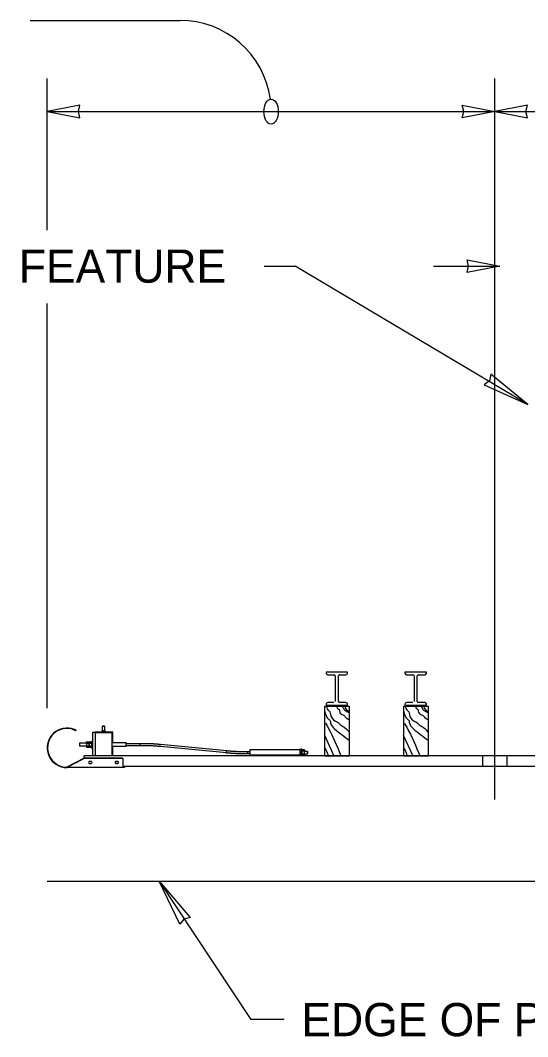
# Model space of a CAD drawing. Extents: x 99862 to 103680, y 99470 to 102076.
# Drawn here: x 100704.8 to 100949.2, y 100910.7 to 101400.9 of the extents above; entities that cross this region are included whole.
import ezdxf

# ---------------------------------------------------------------- set-up
doc = ezdxf.new("R2010")
doc.units = 0
for name, color, linetype in [('Level 10', 7, 'Continuous'), ('Level 11', 7, 'Continuous'), ('Level 13', 7, 'Continuous'), ('Level 15', 7, 'Continuous'), ('Level 2', 7, 'Continuous'), ('Level 20', 7, 'Continuous'), ('Level 21', 7, 'Continuous'), ('Level 3', 7, 'Continuous'), ('Level 4', 7, 'Continuous'), ('Level 5', 7, 'Continuous'), ('Level 6', 7, 'Continuous'), ('Level 7', 7, 'Continuous'), ('Level 9', 7, 'Continuous')]:
    doc.layers.add(name, color=color, linetype=linetype)

msp = doc.modelspace()

# ---------------------------------------------------------------- linework, layer by layer
at = {"layer": 'Level 10'}
for p, q in [((100851.41, 101070.07), (100863.41, 101070.07)), ((100851.41, 101070.07), (100851.41, 101046.07)), ((100863.41, 101046.07), (100863.41, 101070.07)), ((100889.41, 101070.07), (100901.41, 101070.07)), ((100889.41, 101070.07), (100889.41, 101046.07)), ((100901.41, 101046.07), (100901.41, 101070.07)), ((100851.41, 101046.07), (100863.41, 101046.07)), ((100856.47, 101045.99), (100856.47, 101046.07)), ((100856.47, 101045.99), (100856.47, 101046.07)), ((100858.34, 101046.07), (100858.34, 101045.99)), ((100858.34, 101046.07), (100858.34, 101045.99)), ((100889.41, 101046.07), (100901.41, 101046.07)), ((100894.47, 101045.99), (100894.47, 101046.07)), ((100894.47, 101045.99), (100894.47, 101046.07)), ((100896.34, 101046.07), (100896.34, 101045.99)), ((100896.34, 101046.07), (100896.34, 101045.99))]:
    msp.add_line(p, q, dxfattribs=at)
at = {"layer": 'Level 11'}
for p, q in [((100927.46, 101046.07), (100927.46, 101040.99)), ((100939.23, 101046.07), (100939.23, 101040.99))]:
    msp.add_line(p, q, dxfattribs=at)
at = {"layer": 'Level 13'}
for p, q in [((100851.28, 101056.16), (100855.88, 101046.15)), ((100889.28, 101056.16), (100893.88, 101046.15))]:
    msp.add_line(p, q, dxfattribs=at)
for points in [[(100852.16, 101070.06), (100853.44, 101067.79), (100853.89, 101067.38), (100854.24, 101065.99), (100856.37, 101062.97), (100858.28, 101061.88), (100858.69, 101061.34), (100860.82, 101059.88), (100861, 101059.75), (100863.42, 101057.46)], [(100857.13, 101070.06), (100857.95, 101068.71), (100858.35, 101068.54), (100858.52, 101067.83), (100859.76, 101066.06), (100861, 101065.4), (100861.32, 101064.97), (100863.38, 101063.56)], [(100859.83, 101070.08), (100860.24, 101069.39), (100861.15, 101068.1), (100862.14, 101067.51), (100863.31, 101066.77)], [(100861.24, 101070.05), (100861.6, 101068.73), (100863.31, 101067.6)], [(100890.16, 101070.06), (100891.44, 101067.79), (100891.89, 101067.38), (100892.24, 101065.99), (100894.37, 101062.97), (100896.28, 101061.88), (100896.69, 101061.34), (100898.82, 101059.88), (100899, 101059.75), (100901.42, 101057.46)], [(100895.13, 101070.06), (100895.95, 101068.71), (100896.35, 101068.54), (100896.52, 101067.83), (100897.76, 101066.06), (100899, 101065.4), (100899.32, 101064.97), (100901.38, 101063.56)], [(100897.83, 101070.08), (100898.24, 101069.39), (100899.15, 101068.1), (100900.14, 101067.51), (100901.31, 101066.77)], [(100899.24, 101070.05), (100899.6, 101068.73), (100901.31, 101067.6)], [(100851.35, 101067.81), (100853.45, 101063.66), (100853.9, 101063.26), (100854.25, 101061.87), (100856.2, 101059.15), (100863.41, 101053.56)], [(100889.35, 101067.81), (100891.45, 101063.66), (100891.9, 101063.26), (100892.25, 101061.87), (100894.2, 101059.15), (100901.41, 101053.56)], [(100851.81, 101061.95), (100852.96, 101059.94), (100859.37, 101046.01)], [(100889.81, 101061.95), (100890.96, 101059.94), (100897.37, 101046.01)], [(100851.39, 101050.24), (100851.54, 101049.98), (100851.68, 101049.71), (100851.96, 101049.17), (100852.44, 101048.06), (100852.9, 101046.93), (100853.13, 101046.37), (100853.37, 101045.81)], [(100889.39, 101050.24), (100889.54, 101049.98), (100889.68, 101049.71), (100889.96, 101049.17), (100890.44, 101048.06), (100890.9, 101046.93), (100891.13, 101046.37), (100891.37, 101045.81)]]:
    msp.add_spline(points, degree=3, dxfattribs=at)
at = {"layer": 'Level 15'}
for p, q in [((100933.41, 101025.04), (100933.41, 101372.87)), ((100822.19, 101282.31), (100837.28, 101282.31)), ((100949.27, 101215.58), (100837.28, 101282.31)), ((100771.65, 100985.62), (100815.84, 100918.9)), ((100831.84, 100918.9), (100815.84, 100918.9))]:
    msp.add_line(p, q, dxfattribs=at)
for points in [[(100949.27, 101215.58), (100931.42, 101230.12), (100930.75, 101227.03), (100928.28, 101225.04)], [(100771.65, 100985.62), (100786.67, 100968.17), (100783.6, 100967.42), (100781.68, 100964.9)]]:
    msp.add_lwpolyline(points, close=True, dxfattribs=at)
msp.add_ellipse((100825.59, 101356.85), major_axis=(0, -6), ratio=0.57735, dxfattribs=at)
at = {"layer": 'Level 2'}
for p, q in [((100735.54, 101046.04), (100735.54, 101046.07)), ((100965.53, 101046.07), (100735.54, 101046.07)), ((100735.54, 101044.99), (100735.54, 101046.04)), ((100960.44, 101040.98), (100754.27, 101040.98))]:
    msp.add_line(p, q, dxfattribs=at)
at = {"layer": 'Level 20'}
for p, q in [((100709.47, 101400.85), (100781.68, 101400.85)), ((100717.77, 101299.67), (100717.77, 101372.87)), ((100717.77, 101356.85), (100933.41, 101356.85)), ((100933.41, 101356.85), (101283.16, 101356.85)), ((100903.77, 101282.31), (100935.77, 101282.31)), ((100717.77, 101069.13), (100717.77, 101264.31))]:
    msp.add_line(p, q, dxfattribs=at)
for points in [[(100717.77, 101356.85), (100733.5, 101353.77), (100732.77, 101356.85), (100733.5, 101359.94)], [(100933.41, 101356.85), (100917.68, 101353.77), (100918.41, 101356.85), (100917.68, 101359.94)], [(100933.41, 101356.85), (100949.13, 101353.77), (100948.4, 101356.85), (100949.13, 101359.94)], [(100935.77, 101282.31), (100920.05, 101279.23), (100920.77, 101282.31), (100920.05, 101285.39)]]:
    msp.add_lwpolyline(points, close=True, dxfattribs=at)
msp.add_arc((100781.68, 101356.85), 44, 7.8051, 90, dxfattribs=at)
at = {"layer": 'Level 21'}
msp.add_line((101213.04, 100985.46), (100717.77, 100985.46), dxfattribs=at)
at = {"layer": 'Level 3'}
for p, q in [((100744.44, 101060.44), (100744.57, 101060.57)), ((100744.44, 101060.44), (100745.38, 101060.44)), ((100744.44, 101058.26), (100744.44, 101060.44)), ((100744.57, 101060.57), (100745.25, 101060.57)), ((100745.25, 101060.57), (100745.38, 101060.44)), ((100745.38, 101060.44), (100745.38, 101058.26)), ((100729.52, 101059.29), (100729.48, 101059.1)), ((100731.68, 101058.47), (100731.6, 101058.31)), ((100735.52, 101044.99), (100727.27, 101040.62)), ((100753.89, 101044.99), (100735.52, 101044.99)), ((100753.89, 101044.88), (100735.57, 101044.88)), ((100738.68, 101043.47), (100738.35, 101043.47)), ((100738.68, 101042.37), (100738.35, 101042.37)), ((100751.43, 101043.47), (100751.1, 101043.47)), ((100751.43, 101042.37), (100751.1, 101042.37)), ((100754.27, 101044.58), (100754.27, 101044.69)), ((100754.27, 101041.15), (100754.27, 101044.58)), ((100754.27, 101041.15), (100754.27, 101040.43)), ((100754.27, 101040.43), (100735.52, 101040.43))]:
    msp.add_line(p, q, dxfattribs=at)
for radius, end in [(9.56, 270.2805), (9.37, 270)]:
    msp.add_arc((100727.27, 101049.99), radius, 76.3846, end, dxfattribs=at)
for centre, major_axis, start_param, end_param in [((100738.35, 101042.92), (0.68, 0), 1.570796, 4.712389), ((100738.68, 101042.92), (0.68, 0), 4.712389, 7.853982), ((100751.1, 101042.92), (0.68, 0), 1.570796, 4.712389), ((100751.43, 101042.92), (0.68, 0), 4.712389, 7.853982), ((100753.89, 101044.69), (-0.375, 0), 3.141593, 4.712389), ((100753.89, 101044.58), (-0.375, 0), 3.141593, 4.712389)]:
    msp.add_ellipse(centre, major_axis=major_axis, ratio=0.807578, start_param=start_param, end_param=end_param, dxfattribs=at)
for points, degree in [([(100729.48, 101059.1), (100729.56, 101059.08), (100729.73, 101059.04), (100729.97, 101058.97), (100730.2, 101058.9), (100730.42, 101058.82), (100730.63, 101058.75), (100730.82, 101058.67), (100731.08, 101058.56), (100731.35, 101058.43), (100731.56, 101058.33), (100731.59, 101058.31), (100731.6, 101058.31)], 3), ([(100729.52, 101059.29), (100730.75, 101058.99), (100731.68, 101058.47), (100731.68, 101058.47)], 2), ([(100735.57, 101044.88), (100732.84, 101043.39), (100730.1, 101041.91), (100727.36, 101040.45), (100727.34, 101040.45), (100727.33, 101040.44), (100727.32, 101040.43)], 3), ([(100754.64, 101040.72), (100754.61, 101040.7), (100754.55, 101040.67), (100754.47, 101040.64), (100754.37, 101040.62), (100754.31, 101040.62), (100754.27, 101040.62)], 3), ([(100755.09, 101040.98), (100754.8, 101040.81), (100754.64, 101040.72)], 2), ([(100755.46, 101040.98), (100755.32, 101040.89), (100755.19, 101040.82), (100754.9, 101040.65), (100754.74, 101040.56)], 3), ([(100735.52, 101040.43), (100732.77, 101040.43), (100730.02, 101040.43), (100727.27, 101040.43)], 2), ([(100727.32, 101040.43), (100727.32, 101040.43), (100727.32, 101040.43), (100727.32, 101040.43)], 2), ([(100754.74, 101040.56), (100754.59, 101040.47), (100754.46, 101040.43), (100754.27, 101040.43)], 2), ([(100754.27, 101040.43), (100754.27, 101040.43), (100754.27, 101040.43), (100754.27, 101040.43)], 2)]:
    msp.add_open_spline(points, degree=degree, dxfattribs=at)
at = {"layer": 'Level 4'}
for p, q in [((100744.1, 101057.57), (100740.79, 101057.57)), ((100742.66, 101057.29), (100740.79, 101057.29)), ((100749.04, 101057.19), (100740.79, 101057.19)), ((100740.79, 101057.19), (100740.79, 101046.07)), ((100749.41, 101057.57), (100745.72, 101057.57)), ((100749.13, 101057.29), (100747.16, 101057.29)), ((100749.04, 101046.07), (100749.04, 101057.19)), ((100749.13, 101052.51), (100749.13, 101057.29)), ((100749.41, 101052.51), (100749.41, 101057.57)), ((100749.13, 101046.07), (100749.13, 101050.63)), ((100749.41, 101046.07), (100749.41, 101050.63))]:
    msp.add_line(p, q, dxfattribs=at)
at = {"layer": 'Level 5'}
for p, q in [((100747.16, 101057.44), (100742.66, 101057.44)), ((100742.66, 101057.44), (100742.66, 101057.19)), ((100747.16, 101057.44), (100747.16, 101057.19))]:
    msp.add_line(p, q, dxfattribs=at)
at = {"layer": 'Level 6'}
for p, q in [((100733.41, 101052.19), (100733.54, 101052.32)), ((100733.41, 101050.95), (100733.41, 101052.19)), ((100733.41, 101052.19), (100733.41, 101052.19)), ((100733.54, 101050.82), (100733.41, 101050.95)), ((100733.54, 101050.82), (100733.54, 101052.32)), ((100733.54, 101052.32), (100736.69, 101052.32)), ((100736.69, 101050.82), (100733.54, 101050.82)), ((100749.04, 101052.51), (100755.82, 101052.51)), ((100755.82, 101050.63), (100749.04, 101050.63)), ((100755.82, 101050.63), (100755.82, 101052.51)), ((100755.82, 101052.51), (100755.82, 101052.51)), ((100755.82, 101052.13), (100762.37, 101052.13)), ((100762.37, 101051.01), (100755.82, 101051.01)), ((100762.37, 101052.13), (100762.37, 101051.01)), ((100804.16, 101047.52), (100772.3, 101050.58)), ((100772.4, 101051.7), (100804.27, 101048.64)), ((100814.2, 101048.21), (100814.2, 101047.09)), ((100814.2, 101048.21), (100815.41, 101048.21)), ((100815.41, 101047.09), (100814.2, 101047.09)), ((100815.41, 101049.19), (100839.41, 101049.19)), ((100815.41, 101049.19), (100815.41, 101046.56)), ((100815.41, 101046.56), (100839.41, 101046.56)), ((100815.41, 101046.56), (100815.41, 101046.07)), ((100839.41, 101049.34), (100840.16, 101049.34)), ((100839.41, 101049.34), (100839.41, 101046.07)), ((100840.16, 101049.34), (100840.16, 101046.07)), ((100841.72, 101048.4), (100843.02, 101048.4)), ((100843.02, 101046.9), (100841.72, 101046.9)), ((100843.02, 101048.4), (100843.02, 101046.9)), ((100843.02, 101048.4), (100843.16, 101048.27)), ((100843.16, 101047.03), (100843.02, 101046.9)), ((100843.16, 101048.27), (100843.16, 101047.03)), ((100843.16, 101047.03), (100843.16, 101047.03))]:
    msp.add_line(p, q, dxfattribs=at)
for centre, start_param in [((100772.35, 101051.14), 3.141597), ((100804.22, 101048.08), 3.141588)]:
    msp.add_ellipse(centre, major_axis=(-0.054, -0.56), ratio=0.548823, start_param=start_param, end_param=6.283185, dxfattribs=at)
for points in [[(100762.37, 101052.13), (100765.91, 101052.13), (100769.45, 101051.98), (100772.4, 101051.7)], [(100772.3, 101050.58), (100769.38, 101050.86), (100765.88, 101051.01), (100762.37, 101051.01)], [(100814.2, 101047.09), (100810.66, 101047.09), (100807.12, 101047.24), (100804.16, 101047.52)], [(100804.27, 101048.64), (100807.19, 101048.36), (100810.69, 101048.21), (100814.2, 101048.21)]]:
    msp.add_open_spline(points, degree=2, dxfattribs=at)
at = {"layer": 'Level 7'}
for p, q in [((100739.57, 101057.57), (100739.57, 101046.07)), ((100739.57, 101057.57), (100740.79, 101057.57)), ((100740.79, 101057.57), (100740.79, 101057.19))]:
    msp.add_line(p, q, dxfattribs=at)
at = {"layer": 'Level 9'}
for p, q in [((100856.51, 101084.64), (100856.5, 101078.5)), ((100858.04, 101078.5), (100858.05, 101084.64)), ((100894.51, 101084.64), (100894.5, 101078.5)), ((100896.04, 101078.5), (100896.05, 101084.64)), ((100856.5, 101078.5), (100856.49, 101072.37)), ((100858.04, 101072.37), (100858.04, 101078.5)), ((100894.5, 101078.5), (100894.49, 101072.37)), ((100896.04, 101072.37), (100896.04, 101078.5)), ((100744.1, 101058.2), (100744.21, 101058.26)), ((100744.1, 101058.2), (100744.1, 101057.44)), ((100744.91, 101058.26), (100744.21, 101058.26)), ((100744.51, 101058.2), (100744.51, 101057.44)), ((100745.51, 101058.26), (100744.91, 101058.26)), ((100745.32, 101058.2), (100745.32, 101057.44)), ((100745.38, 101058.78), (100745.38, 101058.78)), ((100745.38, 101058.78), (100745.38, 101058.78)), ((100745.51, 101058.26), (100745.53, 101058.26)), ((100745.61, 101058.26), (100745.53, 101058.26)), ((100745.61, 101058.26), (100745.72, 101058.2)), ((100745.72, 101058.2), (100745.72, 101057.44)), ((100749.04, 101056.54), (100749.13, 101056.54)), ((100749.13, 101055.6), (100749.04, 101055.6)), ((100736.69, 101052.7), (100736.79, 101052.87)), ((100736.69, 101052.7), (100736.69, 101052.56)), ((100736.69, 101052.53), (100736.69, 101052.56)), ((100736.69, 101052.53), (100736.69, 101051.57)), ((100736.69, 101051.57), (100736.69, 101050.45)), ((100736.79, 101050.27), (100736.69, 101050.45)), ((100736.79, 101052.87), (100738, 101052.87)), ((100736.79, 101052.22), (100738, 101052.22)), ((100736.79, 101050.92), (100738, 101050.92)), ((100738, 101052.7), (100738.11, 101052.87)), ((100738, 101052.22), (100738, 101052.87)), ((100738, 101052.53), (100738, 101052.56)), ((100738, 101050.92), (100738, 101052.22)), ((100738, 101051.57), (100738, 101051.57)), ((100738, 101051.57), (100738, 101051.57)), ((100738, 101050.27), (100738, 101050.92)), ((100738.11, 101050.27), (100738, 101050.45)), ((100738.11, 101052.87), (100739.32, 101052.87)), ((100738.11, 101052.22), (100739.32, 101052.22)), ((100738.11, 101050.92), (100739.32, 101050.92)), ((100739.32, 101053.24), (100739.57, 101053.24)), ((100739.32, 101049.9), (100739.32, 101053.24)), ((100739.32, 101052.87), (100739.32, 101053.24)), ((100739.32, 101052.22), (100739.32, 101052.87)), ((100739.32, 101050.92), (100739.32, 101052.22)), ((100739.32, 101050.27), (100739.32, 101050.92)), ((100736.79, 101050.27), (100738, 101050.27)), ((100738.11, 101050.27), (100739.32, 101050.27)), ((100739.32, 101049.9), (100739.57, 101049.9)), ((100840.41, 101049.31), (100840.16, 101049.31)), ((100840.41, 101049.31), (100840.41, 101046.07)), ((100841.62, 101048.95), (100840.41, 101048.95)), ((100840.41, 101048.95), (100840.41, 101048.3)), ((100841.62, 101048.3), (100840.41, 101048.3)), ((100840.41, 101048.3), (100840.41, 101047)), ((100840.41, 101047), (100840.41, 101046.35)), ((100841.62, 101047), (100840.41, 101047)), ((100840.41, 101046.35), (100840.41, 101046.07)), ((100841.62, 101046.35), (100840.41, 101046.35)), ((100841.62, 101048.95), (100841.72, 101048.77)), ((100841.72, 101046.52), (100841.62, 101046.35)), ((100841.72, 101047.65), (100841.72, 101048.77)), ((100841.72, 101046.69), (100841.72, 101047.65)), ((100841.72, 101046.69), (100841.72, 101046.66)), ((100841.72, 101046.52), (100841.72, 101046.66))]:
    msp.add_line(p, q, dxfattribs=at)
for points in [[(100857.28, 101086.5), (100852.11, 101086.51), (100852.11, 101086.03)], [(100852.9, 101085.24), (100855.92, 101085.23)], [(100862.45, 101086.01), (100862.45, 101086.5), (100857.28, 101086.5)], [(100858.64, 101085.23), (100861.66, 101085.23)], [(100895.28, 101086.5), (100890.11, 101086.51), (100890.11, 101086.03)], [(100890.9, 101085.24), (100893.92, 101085.23)], [(100900.45, 101086.01), (100900.45, 101086.5), (100895.28, 101086.5)], [(100896.64, 101085.23), (100899.66, 101085.23)], [(100852.09, 101070.99), (100852.09, 101070.51), (100857.26, 101070.5)], [(100855.9, 101071.78), (100852.88, 101071.78)], [(100857.26, 101070.5), (100862.43, 101070.5), (100862.43, 101070.98)], [(100861.64, 101071.77), (100858.63, 101071.77)], [(100890.09, 101070.99), (100890.09, 101070.51), (100895.26, 101070.5)], [(100893.9, 101071.78), (100890.88, 101071.78)], [(100895.26, 101070.5), (100900.43, 101070.5), (100900.43, 101070.98)], [(100899.64, 101071.77), (100896.63, 101071.77)]]:
    msp.add_lwpolyline(points, dxfattribs=at)
for centre, radius, start, end in [((100852.9, 101086.03), 0.788, 179.9273, 269.9273), ((100855.92, 101084.64), 0.591, 359.9273, 89.9273), ((100858.64, 101084.64), 0.591, 89.9273, 179.9273), ((100861.66, 101086.01), 0.788, 269.9273, 359.9273), ((100890.9, 101086.03), 0.788, 179.9273, 269.9273), ((100893.92, 101084.64), 0.591, 359.9273, 89.9273), ((100896.64, 101084.64), 0.591, 89.9273, 179.9273), ((100899.66, 101086.01), 0.788, 269.9273, 359.9273), ((100852.88, 101070.99), 0.788, 89.9273, 179.9478), ((100858.63, 101072.36), 0.591, 179.9273, 269.9273), ((100861.64, 101070.98), 0.788, 359.9478, 89.9273), ((100890.88, 101070.99), 0.788, 89.9273, 179.9478), ((100896.63, 101072.36), 0.591, 179.9273, 269.9273), ((100899.64, 101070.98), 0.788, 359.9478, 89.9273)]:
    msp.add_arc(centre, radius, start, end, dxfattribs=at)
for points, degree in [([(100744.1, 101058.2), (100744.17, 101058.24), (100744.23, 101058.26), (100744.37, 101058.26), (100744.44, 101058.24), (100744.51, 101058.2)], 3), ([(100744.1, 101058.2), (100744.1, 101058.2), (100744.1, 101058.2), (100744.1, 101058.2)], 2), ([(100744.91, 101058.26), (100744.77, 101058.26), (100744.64, 101058.24), (100744.51, 101058.2)], 2), ([(100745.32, 101058.2), (100745.18, 101058.24), (100745.05, 101058.26), (100744.91, 101058.26)], 2), ([(100745.32, 101058.2), (100745.38, 101058.24), (100745.45, 101058.26), (100745.51, 101058.26)], 2), ([(100745.53, 101058.26), (100745.59, 101058.26), (100745.66, 101058.24), (100745.72, 101058.2)], 2), ([(100745.72, 101058.2), (100745.72, 101058.2), (100745.72, 101058.2), (100745.72, 101058.2)], 2), ([(100736.69, 101052.56), (100736.7, 101052.66), (100736.73, 101052.77), (100736.79, 101052.87)], 2), ([(100736.79, 101052.22), (100736.73, 101052.32), (100736.7, 101052.43), (100736.69, 101052.53)], 2), ([(100736.79, 101052.22), (100736.73, 101052.01), (100736.69, 101051.79), (100736.69, 101051.57)], 2), ([(100736.69, 101051.57), (100736.69, 101051.35), (100736.73, 101051.13), (100736.79, 101050.92)], 2), ([(100736.79, 101050.27), (100736.73, 101050.38), (100736.69, 101050.48), (100736.69, 101050.71), (100736.73, 101050.81), (100736.79, 101050.92)], 3), ([(100738, 101052.56), (100738.01, 101052.66), (100738.05, 101052.77), (100738.11, 101052.87)], 2), ([(100738.11, 101052.22), (100738.05, 101052.32), (100738.01, 101052.43), (100738, 101052.53)], 2), ([(100738.11, 101052.22), (100738.04, 101052.01), (100738, 101051.79), (100738, 101051.57)], 2), ([(100738, 101051.57), (100738, 101051.35), (100738.04, 101051.13), (100738.11, 101050.92)], 2), ([(100738.11, 101050.27), (100738.04, 101050.38), (100738.01, 101050.48), (100738, 101050.71), (100738.04, 101050.81), (100738.11, 101050.92)], 3), ([(100736.79, 101050.27), (100736.79, 101050.27), (100736.79, 101050.27), (100736.79, 101050.27)], 2), ([(100738.11, 101050.27), (100738.11, 101050.27), (100738.11, 101050.27), (100738.11, 101050.27)], 2), ([(100841.62, 101048.95), (100841.62, 101048.95), (100841.62, 101048.95), (100841.62, 101048.95)], 2), ([(100841.62, 101048.95), (100841.68, 101048.84), (100841.72, 101048.73), (100841.72, 101048.51), (100841.68, 101048.4), (100841.62, 101048.3)], 3), ([(100841.72, 101047.65), (100841.72, 101047.87), (100841.68, 101048.09), (100841.62, 101048.3)], 2), ([(100841.62, 101047), (100841.68, 101047.21), (100841.72, 101047.43), (100841.72, 101047.65)], 2), ([(100841.62, 101047), (100841.68, 101046.9), (100841.72, 101046.79), (100841.72, 101046.69)], 2), ([(100841.72, 101046.66), (100841.72, 101046.56), (100841.68, 101046.45), (100841.62, 101046.35)], 2), ([(100841.62, 101046.35), (100841.62, 101046.35), (100841.62, 101046.35), (100841.62, 101046.35)], 2)]:
    msp.add_open_spline(points, degree=degree, dxfattribs=at)

# ---------------------------------------------------------------- texts
at = {"layer": 'Level 20'}
for s, p in [('FIXED FEATURE', (100635.13, 101274.31)), ('EDGE OF PAVEMENT', (100840.22, 100910.9))]:
    msp.add_text(s, height=16, dxfattribs=at).set_placement(p)

doc.saveas('drawing.dxf')
